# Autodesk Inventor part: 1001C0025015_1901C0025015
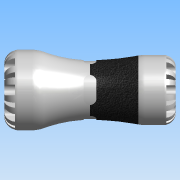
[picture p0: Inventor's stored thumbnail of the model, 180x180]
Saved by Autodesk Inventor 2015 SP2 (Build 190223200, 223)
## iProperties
Created: 2016-12
Part Number: 1001C0025015_1901C0025015
Material: PVC-Piping
Description: PLASSON COPPER PIPE ADAPTOR 25X15 SERIES 1
Document SubType Name: Modeling
Designer: KIM
Mass: 95.2094 g
Surface Area: 200.83 cm^2
Volume: 68.0067 cm^3
Density: 1.4 g/cm^3
Appearance: Smooth - White
ILogicFactory: False
Author: KIM
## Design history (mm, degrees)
derived "1001C.ipt"
feature "Solid1::1001C.ipt"
tag "TaggingFeature1"
body "Solid1"
other parameters: "d1" = 47, "d2" = 48, "d11" = 6.3, "d13" = 6.3, "d14" = 0, "d16" = 360 deg, "d18" = 8 deg, "d19" = 0.5, "d20" = 8 deg, "d21" = 0.5, "d23" = 0, "d25" = 360 deg, "d27" = 18.8, "d28" = 5, "d29" = 7.5, "d30" = 12.348, "d31" = 0, "d33" = 0, "d38" = 0.47, "d44" = 25, "d46" = 34.85, "d47" = 47, "d50" = 360 deg, "d54" = 0.513, "d60" = 15, "d61" = 27.5, "d62" = 41, "d65" = 46, "d66" = 1.25, "d70" = 5.4, "d72" = 5.4, "d73" = 0, "d75" = 360 deg, "d77" = 8 deg, "d78" = 8 deg, "d79" = 0.5, "d80" = 0.5, "d82" = 0, "d84" = 360 deg, "d87" = 31.25, "d_" = 25, "E_" = 47, "l_" = 48, "d_1" = 15, "E_1" = 41, "l_1" = 46, "d12" = 31.25, "d42" = 47, "d52" = 7.875, "d68" = 41, "d69" = 27.5, "d71" = 6.75
